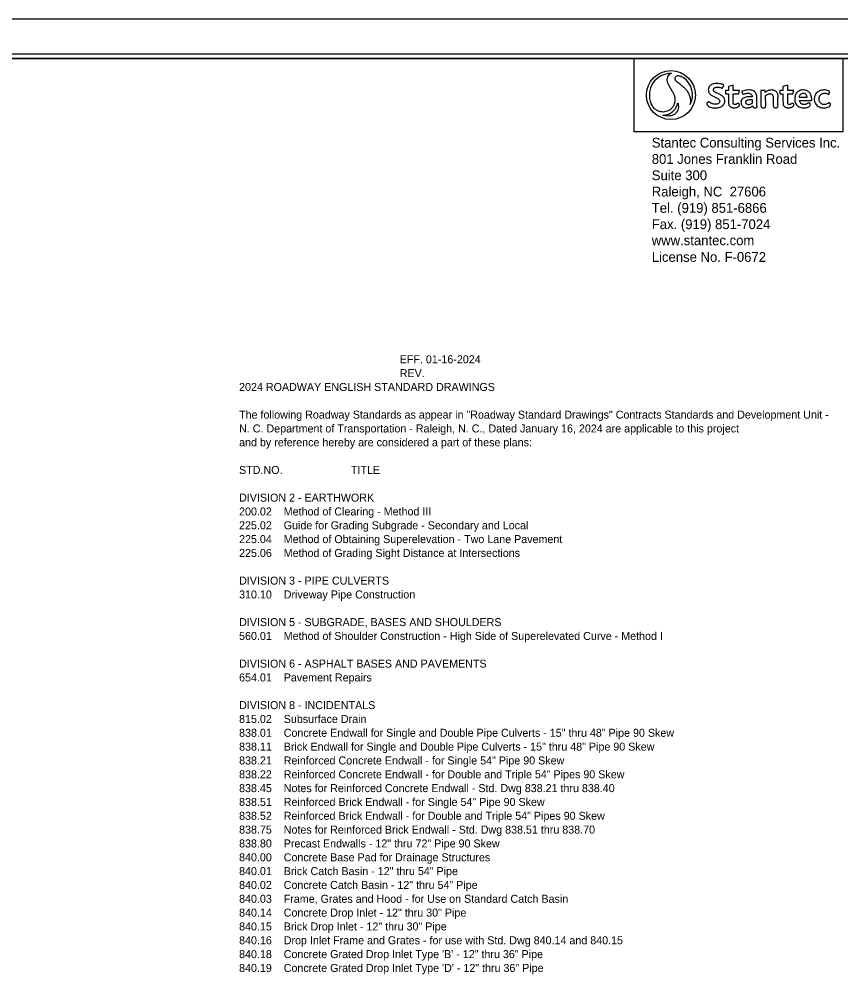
# Model space of a CAD drawing. Extents: x 1877070 to 1879304, y 464355 to 465670.
# Drawn here: x 1878265 to 1878829, y 465012 to 465670 of the extents above; entities that cross this region are included whole.
import ezdxf

# ---------------------------------------------------------------- set-up
doc = ezdxf.new("R2010")
doc.units = 0
for name, color, linetype in [('Prop AutoTurn Projected Path', 7, 'Continuous'), ('Prop EOT', 7, 'Continuous'), ('Prop Horizontal Alignment', 7, 'Continuous'), ('Prop Horizontal Alignment Curve and Spiral Data', 7, 'Continuous'), ('Prop Horizontal Alignment Tick Small', 7, 'Continuous'), ('Prop Lane Lines', 7, 'Continuous'), ('Scratch_Level_0', 7, 'Continuous')]:
    doc.layers.add(name, color=color, linetype=linetype)

msp = doc.modelspace()

# ---------------------------------------------------------------- linework, layer by layer
at = {"layer": 'Prop AutoTurn Projected Path'}
msp.add_lwpolyline([(1877069.97, 464355.13), (1879090.77, 464355.13), (1879090.77, 465669.52), (1877069.97, 465669.52)], close=True, dxfattribs=at)
at = {"layer": 'Prop EOT'}
msp.add_line((1877269.83, 465642.52), (1879070.4, 465642.53), dxfattribs=at)
at = {"layer": 'Prop Horizontal Alignment'}
for p, q in [((1878747.66, 465622.05), (1878748.49, 465624.39)), ((1878755.09, 465624.25), (1878751.78, 465623.33)), ((1878755.09, 465620.58), (1878755.09, 465624.25)), ((1878792.48, 465624.26), (1878789.17, 465623.33)), ((1878792.48, 465620.58), (1878792.48, 465624.26)), ((1878751.78, 465620.58), (1878749.68, 465620.58)), ((1878749.68, 465620.58), (1878749.68, 465618.27)), ((1878749.68, 465618.27), (1878751.8, 465618.27)), ((1878751.78, 465623.33), (1878751.78, 465620.58)), ((1878755.02, 465612.46), (1878755.07, 465618.27)), ((1878755.07, 465618.27), (1878758.57, 465618.27)), ((1878759.37, 465620.58), (1878755.09, 465620.58)), ((1878758.57, 465618.27), (1878759.37, 465620.58)), ((1878760.75, 465619.74), (1878761.76, 465617.79)), ((1878776.85, 465620.57), (1878774.06, 465620.57)), ((1878774.06, 465620.57), (1878774.06, 465610.02)), ((1878777.03, 465619.17), (1878776.85, 465620.57)), ((1878789.17, 465620.58), (1878787.07, 465620.58)), ((1878787.07, 465620.58), (1878787.07, 465618.28)), ((1878787.07, 465618.28), (1878789.19, 465618.28)), ((1878789.17, 465623.33), (1878789.17, 465620.58)), ((1878792.42, 465612.46), (1878792.46, 465618.28)), ((1878792.46, 465618.28), (1878795.96, 465618.28)), ((1878796.76, 465620.58), (1878792.48, 465620.58)), ((1878795.96, 465618.28), (1878796.76, 465620.58)), ((1878820.63, 465617.72), (1878821.37, 465619.88)), ((1878767.98, 465614.32), (1878767.98, 465611.71)), ((1878777.31, 465610.02), (1878777.3, 465616.98)), ((1878805.57, 465615.66), (1878800.52, 465615.66)), ((1878800.52, 465613.64), (1878808.92, 465613.64))]:
    msp.add_line(p, q, dxfattribs=at)
for points in [[(1878712.54, 465632.16), (1878712.54, 465632.16)], [(1878721.05, 465629.26), (1878721.05, 465629.25)]]:
    msp.add_lwpolyline(points, dxfattribs=at)
msp.add_circle((1878712.22, 465617.35), 16.81, dxfattribs=at)
for start, end in [(88.77376, 203.69163), (88.76731, 88.77376), (333.78865, 53.43978), (247.12556, 251.46513)]:
    msp.add_arc((1878712.22, 465617.35), 14.82, start, end, dxfattribs=at)
for points, degree in [([(1878712.54, 465632.16), (1878712.18, 465632.09), (1878711.34, 465631.91), (1878710.24, 465630.79), (1878709.42, 465628.95), (1878709.53, 465626.88), (1878710.26, 465624.88), (1878711.37, 465622.94), (1878712.51, 465620.79), (1878713.78, 465618.76), (1878714.66, 465616.71), (1878715.08, 465614.47), (1878714.8, 465612.23), (1878714.16, 465610.18), (1878712.89, 465608.31), (1878711.23, 465606.98), (1878709.49, 465606.2), (1878707.92, 465605.72), (1878706.17, 465605.72), (1878704.22, 465605.99), (1878702.29, 465606.87), (1878700.24, 465608.61), (1878699.26, 465610.31), (1878698.65, 465611.4)], 3), ([(1878712.54, 465632.16), (1878712.54, 465632.16), (1878712.54, 465632.16), (1878712.54, 465632.16)], 2), ([(1878725.52, 465610.81), (1878725.65, 465611.33), (1878725.87, 465612.3), (1878725.83, 465613.87), (1878725.67, 465615.24), (1878725.27, 465616.52), (1878724.79, 465618), (1878723.95, 465619.6), (1878722.76, 465621.11), (1878721.2, 465622.7), (1878719.25, 465624.12), (1878717.25, 465625.76), (1878715.64, 465626.97), (1878715.07, 465628.39), (1878715.07, 465629.47), (1878715.6, 465630.2), (1878716.31, 465630.71), (1878717.26, 465630.79), (1878718.38, 465630.58), (1878719.67, 465630.03), (1878720.57, 465629.53), (1878721.05, 465629.26)], 3), ([(1878748.49, 465624.39), (1878748.34, 465624.46), (1878747.69, 465624.77), (1878746.44, 465625.1), (1878744.91, 465625.29), (1878743.52, 465625.36), (1878742.36, 465625.25), (1878741.25, 465625.02), (1878740.18, 465624.59), (1878739.15, 465623.89), (1878738.41, 465622.94), (1878737.99, 465621.98), (1878737.9, 465621.09), (1878737.94, 465620.27), (1878738.11, 465619.48), (1878738.45, 465618.83), (1878738.85, 465618.25), (1878739.35, 465617.72), (1878739.95, 465617.23), (1878740.7, 465616.78), (1878741.62, 465616.31), (1878742.64, 465615.84), (1878743.67, 465615.4), (1878744.53, 465614.96), (1878745.16, 465614.42), (1878745.59, 465613.92), (1878745.74, 465613.3), (1878745.72, 465612.72), (1878745.49, 465612.08), (1878744.95, 465611.54), (1878744.1, 465611.17), (1878743.09, 465611.03), (1878741.98, 465611.08), (1878740.99, 465611.28), (1878740.19, 465611.68), (1878739.55, 465611.94), (1878739.11, 465612.35), (1878738.69, 465612.51), (1878738.32, 465612.67), (1878737.91, 465612.65), (1878737.5, 465612.52), (1878737.15, 465612.22), (1878736.92, 465611.79), (1878736.91, 465611.32), (1878736.98, 465610.86), (1878737.34, 465610.37), (1878738.04, 465609.66), (1878739.29, 465609.05), (1878740.83, 465608.64), (1878742.39, 465608.56), (1878743.74, 465608.6), (1878744.92, 465608.75), (1878745.95, 465609.06), (1878747.02, 465609.55), (1878748.06, 465610.36), (1878748.86, 465611.36), (1878749.19, 465612.55), (1878749.24, 465613.62), (1878749.11, 465614.59), (1878748.73, 465615.37), (1878748.26, 465616.15), (1878747.46, 465616.81), (1878746.55, 465617.42), (1878745.54, 465617.9), (1878744.45, 465618.41), (1878743.32, 465618.9), (1878742.36, 465619.41), (1878741.71, 465619.99), (1878741.44, 465620.56), (1878741.39, 465621.16), (1878741.56, 465621.71), (1878741.93, 465622.18), (1878742.45, 465622.52), (1878743.13, 465622.77), (1878743.94, 465622.83), (1878744.74, 465622.8), (1878745.54, 465622.67), (1878746.31, 465622.51), (1878747.04, 465622.29), (1878747.47, 465622.12), (1878747.66, 465622.05)], 3), ([(1878751.8, 465618.27), (1878751.79, 465616.22), (1878751.78, 465614.05), (1878751.81, 465611.63), (1878751.92, 465611.05), (1878752.15, 465610.26), (1878752.59, 465609.72), (1878753.05, 465609.3), (1878753.53, 465608.98), (1878754.3, 465608.71), (1878755.36, 465608.59), (1878756.45, 465608.64), (1878757.54, 465608.79), (1878758.37, 465609.21), (1878758.98, 465609.71), (1878759.27, 465610.27), (1878759.3, 465610.77), (1878759.21, 465611.19), (1878758.99, 465611.43), (1878758.73, 465611.59), (1878758.42, 465611.65), (1878758.09, 465611.65), (1878757.76, 465611.57), (1878757.46, 465611.33), (1878757.13, 465611.08), (1878756.72, 465610.9), (1878756.29, 465610.76), (1878755.84, 465610.81), (1878755.44, 465611.02), (1878755.14, 465611.33), (1878755.01, 465611.85), (1878755.02, 465612.22), (1878755.02, 465612.46)], 3), ([(1878768.3, 465610.08), (1878768.31, 465609.96), (1878768.33, 465609.69), (1878768.61, 465609.29), (1878768.99, 465608.84), (1878769.7, 465608.51), (1878770.44, 465608.53), (1878771.13, 465608.69), (1878771.4, 465609.23), (1878771.41, 465609.78), (1878771.26, 465610.52), (1878771.09, 465612.54), (1878771.22, 465614.68), (1878771.18, 465616.99), (1878770.91, 465618.11), (1878770.28, 465619.12), (1878769.6, 465619.89), (1878768.49, 465620.46), (1878767.1, 465620.82), (1878765.46, 465620.92), (1878763.8, 465620.76), (1878762.2, 465620.39), (1878761.22, 465619.95), (1878760.75, 465619.74)], 3), ([(1878761.76, 465617.79), (1878761.91, 465617.87), (1878762.37, 465618.11), (1878763.12, 465618.34), (1878764.02, 465618.57), (1878764.88, 465618.64), (1878765.77, 465618.6), (1878766.57, 465618.35), (1878767.27, 465617.95), (1878767.76, 465617.36), (1878767.97, 465616.77), (1878767.97, 465616.4), (1878767.97, 465616.27)], 3), ([(1878777.3, 465616.98), (1878777.36, 465617.03), (1878777.59, 465617.24), (1878778.13, 465617.57), (1878778.83, 465618.04), (1878779.72, 465618.31), (1878780.63, 465618.3), (1878781.5, 465618.02), (1878782.1, 465617.39), (1878782.43, 465616.65), (1878782.59, 465615.65), (1878782.49, 465614.14), (1878782.56, 465612.24), (1878782.47, 465610.65), (1878782.53, 465609.55), (1878782.91, 465608.96), (1878783.57, 465608.54), (1878784.33, 465608.56), (1878785.07, 465608.74), (1878785.66, 465609.19), (1878785.84, 465610.06), (1878785.71, 465611.59), (1878785.79, 465613.48), (1878785.75, 465615.55), (1878785.82, 465616.87), (1878785.64, 465618.02), (1878785.29, 465618.82), (1878784.72, 465619.65), (1878783.79, 465620.29), (1878782.64, 465620.84), (1878781.32, 465620.87), (1878780.13, 465620.8), (1878779.06, 465620.45), (1878778.11, 465620.01), (1878777.48, 465619.51), (1878777.14, 465619.25), (1878777.03, 465619.17)], 3), ([(1878789.19, 465618.28), (1878789.19, 465616.22), (1878789.18, 465614.05), (1878789.2, 465611.63), (1878789.31, 465611.05), (1878789.54, 465610.26), (1878789.99, 465609.72), (1878790.44, 465609.3), (1878790.92, 465608.98), (1878791.69, 465608.71), (1878792.75, 465608.6), (1878793.84, 465608.64), (1878794.93, 465608.79), (1878795.77, 465609.22), (1878796.38, 465609.71), (1878796.66, 465610.28), (1878796.69, 465610.77), (1878796.6, 465611.19), (1878796.38, 465611.44), (1878796.12, 465611.59), (1878795.81, 465611.65), (1878795.48, 465611.66), (1878795.15, 465611.57), (1878794.85, 465611.33), (1878794.52, 465611.08), (1878794.11, 465610.91), (1878793.68, 465610.77), (1878793.23, 465610.82), (1878792.84, 465611.03), (1878792.53, 465611.33), (1878792.4, 465611.85), (1878792.41, 465612.23), (1878792.42, 465612.46)], 3), ([(1878808.92, 465613.64), (1878808.93, 465613.95), (1878808.96, 465614.76), (1878808.82, 465616.05), (1878808.49, 465617.51), (1878807.79, 465618.62), (1878807, 465619.6), (1878806, 465620.28), (1878804.74, 465620.79), (1878803.31, 465620.88), (1878801.92, 465620.85), (1878800.59, 465620.43), (1878799.45, 465619.78), (1878798.46, 465618.84), (1878797.79, 465617.7), (1878797.42, 465616.45), (1878797.27, 465615.17), (1878797.26, 465613.8), (1878797.56, 465612.53), (1878798.06, 465611.29), (1878798.83, 465610.23), (1878800, 465609.38), (1878801.46, 465608.66), (1878803.15, 465608.58), (1878804.68, 465608.59), (1878805.99, 465608.87), (1878807.02, 465609.37), (1878807.77, 465610.02), (1878808.05, 465610.73), (1878807.92, 465611.3), (1878807.64, 465611.76), (1878807.19, 465611.89), (1878806.74, 465611.95), (1878806.23, 465611.78), (1878805.62, 465611.4), (1878804.92, 465610.98), (1878804.06, 465610.79), (1878803.27, 465610.77), (1878802.49, 465610.97), (1878801.84, 465611.41), (1878801.2, 465611.94), (1878800.82, 465612.64), (1878800.59, 465613.21), (1878800.54, 465613.53), (1878800.52, 465613.64)], 3), ([(1878800.52, 465615.66), (1878800.52, 465615.77), (1878800.52, 465616.02), (1878800.55, 465616.52), (1878800.72, 465617.15), (1878801.11, 465617.81), (1878801.72, 465618.35), (1878802.56, 465618.65), (1878803.45, 465618.67), (1878804.29, 465618.42), (1878805, 465617.96), (1878805.35, 465617.18), (1878805.53, 465616.41), (1878805.56, 465615.89), (1878805.57, 465615.66)], 3), ([(1878821.37, 465619.88), (1878821.09, 465620.04), (1878820.4, 465620.43), (1878819.06, 465620.78), (1878817.38, 465620.95), (1878815.61, 465620.75), (1878813.91, 465620.19), (1878812.5, 465619.25), (1878811.49, 465617.98), (1878810.86, 465616.51), (1878810.64, 465614.86), (1878810.77, 465613.2), (1878811.34, 465611.7), (1878812.18, 465610.56), (1878813.35, 465609.56), (1878814.95, 465608.81), (1878816.83, 465608.51), (1878818.55, 465608.63), (1878819.98, 465609), (1878821.11, 465609.52), (1878821.84, 465610.23), (1878821.88, 465610.91), (1878821.82, 465611.41), (1878821.48, 465611.72), (1878821.14, 465611.92), (1878820.75, 465611.95), (1878820.23, 465611.87), (1878819.77, 465611.46), (1878819.11, 465611.18), (1878818.43, 465610.87), (1878817.48, 465610.79), (1878816.48, 465610.88), (1878815.51, 465611.4), (1878814.79, 465612.13), (1878814.21, 465613), (1878814.04, 465614.03), (1878813.88, 465615.05), (1878814.17, 465616.06), (1878814.56, 465616.98), (1878815.14, 465617.72), (1878815.91, 465618.26), (1878816.79, 465618.6), (1878817.82, 465618.69), (1878818.85, 465618.59), (1878819.84, 465618.28), (1878820.38, 465617.9), (1878820.63, 465617.72)], 3), ([(1878706.46, 465603.7), (1878706.83, 465603.66), (1878707.69, 465603.58), (1878709.16, 465603.86), (1878710.79, 465604.25), (1878712.27, 465605.11), (1878713.63, 465606.06), (1878714.9, 465607.43), (1878715.97, 465608.96), (1878716.63, 465610.54), (1878716.84, 465611.48), (1878716.94, 465611.93)], 3), ([(1878716.94, 465611.93), (1878717.04, 465611.55), (1878717.32, 465610.59), (1878717.39, 465608.98), (1878717.12, 465607.24), (1878716.21, 465605.65), (1878715, 465604.19), (1878713.25, 465603.39), (1878711.38, 465602.97), (1878709.46, 465602.93), (1878708.14, 465603.18), (1878707.51, 465603.3)], 3), ([(1878767.97, 465616.27), (1878767.76, 465616.27), (1878767.06, 465616.26), (1878765.86, 465616.2), (1878764.44, 465616.13), (1878763.1, 465615.83), (1878761.87, 465615.32), (1878760.8, 465614.39), (1878760.29, 465613.09), (1878760.36, 465611.86), (1878760.56, 465610.8), (1878761.2, 465609.91), (1878762.14, 465609.09), (1878763.47, 465608.59), (1878764.85, 465608.57), (1878766.13, 465608.74), (1878767.11, 465609.08), (1878767.83, 465609.57), (1878768.13, 465609.9), (1878768.3, 465610.08)], 3), ([(1878767.98, 465611.71), (1878767.9, 465611.65), (1878767.59, 465611.41), (1878767.03, 465611.11), (1878766.25, 465610.79), (1878765.41, 465610.73), (1878764.69, 465610.93), (1878764.19, 465611.25), (1878763.86, 465611.64), (1878763.64, 465612.1), (1878763.61, 465612.6), (1878763.7, 465613.09), (1878764, 465613.56), (1878764.5, 465613.87), (1878765.11, 465614.14), (1878765.91, 465614.25), (1878766.73, 465614.29), (1878767.45, 465614.33), (1878767.83, 465614.33), (1878767.98, 465614.32)], 3), ([(1878774.06, 465610.02), (1878774.09, 465609.88), (1878774.16, 465609.57), (1878774.39, 465609.03), (1878774.99, 465608.58), (1878775.81, 465608.57), (1878776.64, 465608.63), (1878777.13, 465609.18), (1878777.31, 465609.65), (1878777.31, 465609.91), (1878777.31, 465610.02)], 3)]:
    msp.add_open_spline(points, degree=degree, dxfattribs=at)
at = {"layer": 'Prop Horizontal Alignment Curve and Spiral Data'}
msp.add_line((1878748.53, 465554.98), (1878748.53, 465554.98), dxfattribs=at)
at = {"layer": 'Prop Horizontal Alignment Tick Small'}
msp.add_lwpolyline([(1878687.04, 465642.53), (1878830.24, 465642.55), (1878830.24, 465592.19), (1878687.05, 465592.17)], close=True, dxfattribs=at)
at = {"layer": 'Prop Lane Lines'}
msp.add_lwpolyline([(1877085.58, 464379.14), (1879085.37, 464379.14), (1879085.37, 465645.52), (1877085.58, 465645.52)], close=True, dxfattribs=at)
at = {"layer": 'Scratch_Level_0'}
msp.add_lwpolyline([(1879070.37, 465642.52), (1877269.83, 465642.52), (1877269.83, 464382.14), (1879070.37, 464382.14)], close=True, dxfattribs=at)

# ---------------------------------------------------------------- texts
at = {"layer": 'Prop Horizontal Alignment'}
for s, height, p in [('Stantec Consulting Services Inc.', 6.7237, (1878699.07, 465581.31)), ('801 Jones Franklin Road', 6.7237, (1878699.07, 465570.11)), ('Suite 300', 6.724, (1878699.07, 465558.91)), ('Raleigh, NC  27606', 6.7237, (1878699.07, 465547.71)), ('Tel. (919) 851-6866', 6.7237, (1878699.07, 465536.5)), ('Fax. (919) 851-7024', 6.7237, (1878699.07, 465525.3)), ('www.stantec.com', 6.7237, (1878699.07, 465514.24)), ('License No. F-0672', 6.7237, (1878699.08, 465502.82))]:
    msp.add_text(s, height=height, rotation=0.00714, dxfattribs=at).set_placement(p)
for s, p in [('                                                      EFF. 01-16-2024', (1878415.62, 465433.15)), ('                                                      REV. ', (1878415.62, 465423.64)), ('2024 ROADWAY ENGLISH STANDARD DRAWINGS', (1878415.62, 465414.14)), ('The following Roadway Standards as appear in "Roadway Standard Drawings" Contracts Standards and Development Unit -', (1878415.62, 465395.14)), ('N. C. Department of Transportation - Raleigh, N. C., Dated January 16, 2024 are applicable to this project', (1878415.62, 465385.64)), ('and by reference hereby are considered a part of these plans:', (1878415.62, 465376.14)), ('STD.NO.                       TITLE', (1878415.62, 465357.14)), ('DIVISION 2 - EARTHWORK', (1878415.62, 465338.13)), ('200.02    Method of Clearing - Method III', (1878415.62, 465328.63)), ('225.02    Guide for Grading Subgrade - Secondary and Local', (1878415.62, 465319.13)), ('225.04    Method of Obtaining Superelevation - Two Lane Pavement', (1878415.62, 465309.63)), ('225.06    Method of Grading Sight Distance at Intersections', (1878415.62, 465300.13)), ('DIVISION 3 - PIPE CULVERTS', (1878415.62, 465281.13)), ('310.10    Driveway Pipe Construction', (1878415.62, 465271.63)), ('DIVISION 5 - SUBGRADE, BASES AND SHOULDERS', (1878415.62, 465252.62)), ('560.01    Method of Shoulder Construction - High Side of Superelevated Curve - Method I', (1878415.62, 465243.12)), ('DIVISION 6 - ASPHALT BASES AND PAVEMENTS', (1878415.62, 465224.12)), ('654.01    Pavement Repairs', (1878415.62, 465214.62)), ('DIVISION 8 - INCIDENTALS', (1878415.62, 465195.62)), ('815.02    Subsurface Drain', (1878415.62, 465186.12)), ('838.01    Concrete Endwall for Single and Double Pipe Culverts - 15" thru 48" Pipe 90 Skew', (1878415.62, 465176.61)), ('838.11    Brick Endwall for Single and Double Pipe Culverts - 15" thru 48" Pipe 90 Skew', (1878415.62, 465167.11)), ('838.21    Reinforced Concrete Endwall - for Single 54" Pipe 90 Skew', (1878415.62, 465157.61)), ('838.22    Reinforced Concrete Endwall - for Double and Triple 54" Pipes 90 Skew', (1878415.62, 465148.11)), ('838.45    Notes for Reinforced Concrete Endwall - Std. Dwg 838.21 thru 838.40', (1878415.62, 465138.61)), ('838.51    Reinforced Brick Endwall - for Single 54" Pipe 90 Skew', (1878415.62, 465129.11)), ('838.52    Reinforced Brick Endwall - for Double and Triple 54" Pipes 90 Skew', (1878415.62, 465119.61)), ('838.75    Notes for Reinforced Brick Endwall - Std. Dwg 838.51 thru 838.70', (1878415.62, 465110.11)), ('838.80    Precast Endwalls - 12" thru 72" Pipe 90 Skew', (1878415.62, 465100.6)), ('840.00    Concrete Base Pad for Drainage Structures', (1878415.62, 465091.1)), ('840.01    Brick Catch Basin - 12" thru 54" Pipe', (1878415.62, 465081.6)), ('840.02    Concrete Catch Basin - 12" thru 54" Pipe', (1878415.62, 465072.1)), ('840.03    Frame, Grates and Hood - for Use on Standard Catch Basin', (1878415.62, 465062.6)), ('840.14    Concrete Drop Inlet - 12" thru 30" Pipe', (1878415.62, 465053.1)), ('840.15    Brick Drop Inlet - 12" thru 30" Pipe', (1878415.62, 465043.6)), ('840.16    Drop Inlet Frame and Grates - for use with Std. Dwg 840.14 and 840.15', (1878415.62, 465034.1)), ('840.18    Concrete Grated Drop Inlet Type \'B\' - 12" thru 36" Pipe', (1878415.62, 465024.6)), ('840.19    Concrete Grated Drop Inlet Type \'D\' - 12" thru 36" Pipe', (1878415.62, 465015.09))]:
    msp.add_text(s, height=5.5, dxfattribs=at).set_placement(p)

doc.saveas('drawing.dxf')
